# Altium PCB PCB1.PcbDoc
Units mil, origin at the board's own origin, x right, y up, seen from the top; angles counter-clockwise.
Board outline 4000.03 x 4245.03 mil, 2 copper layers (Top Layer, Bottom Layer); 64 components, 62 nets, 248 pads, 35 vias.
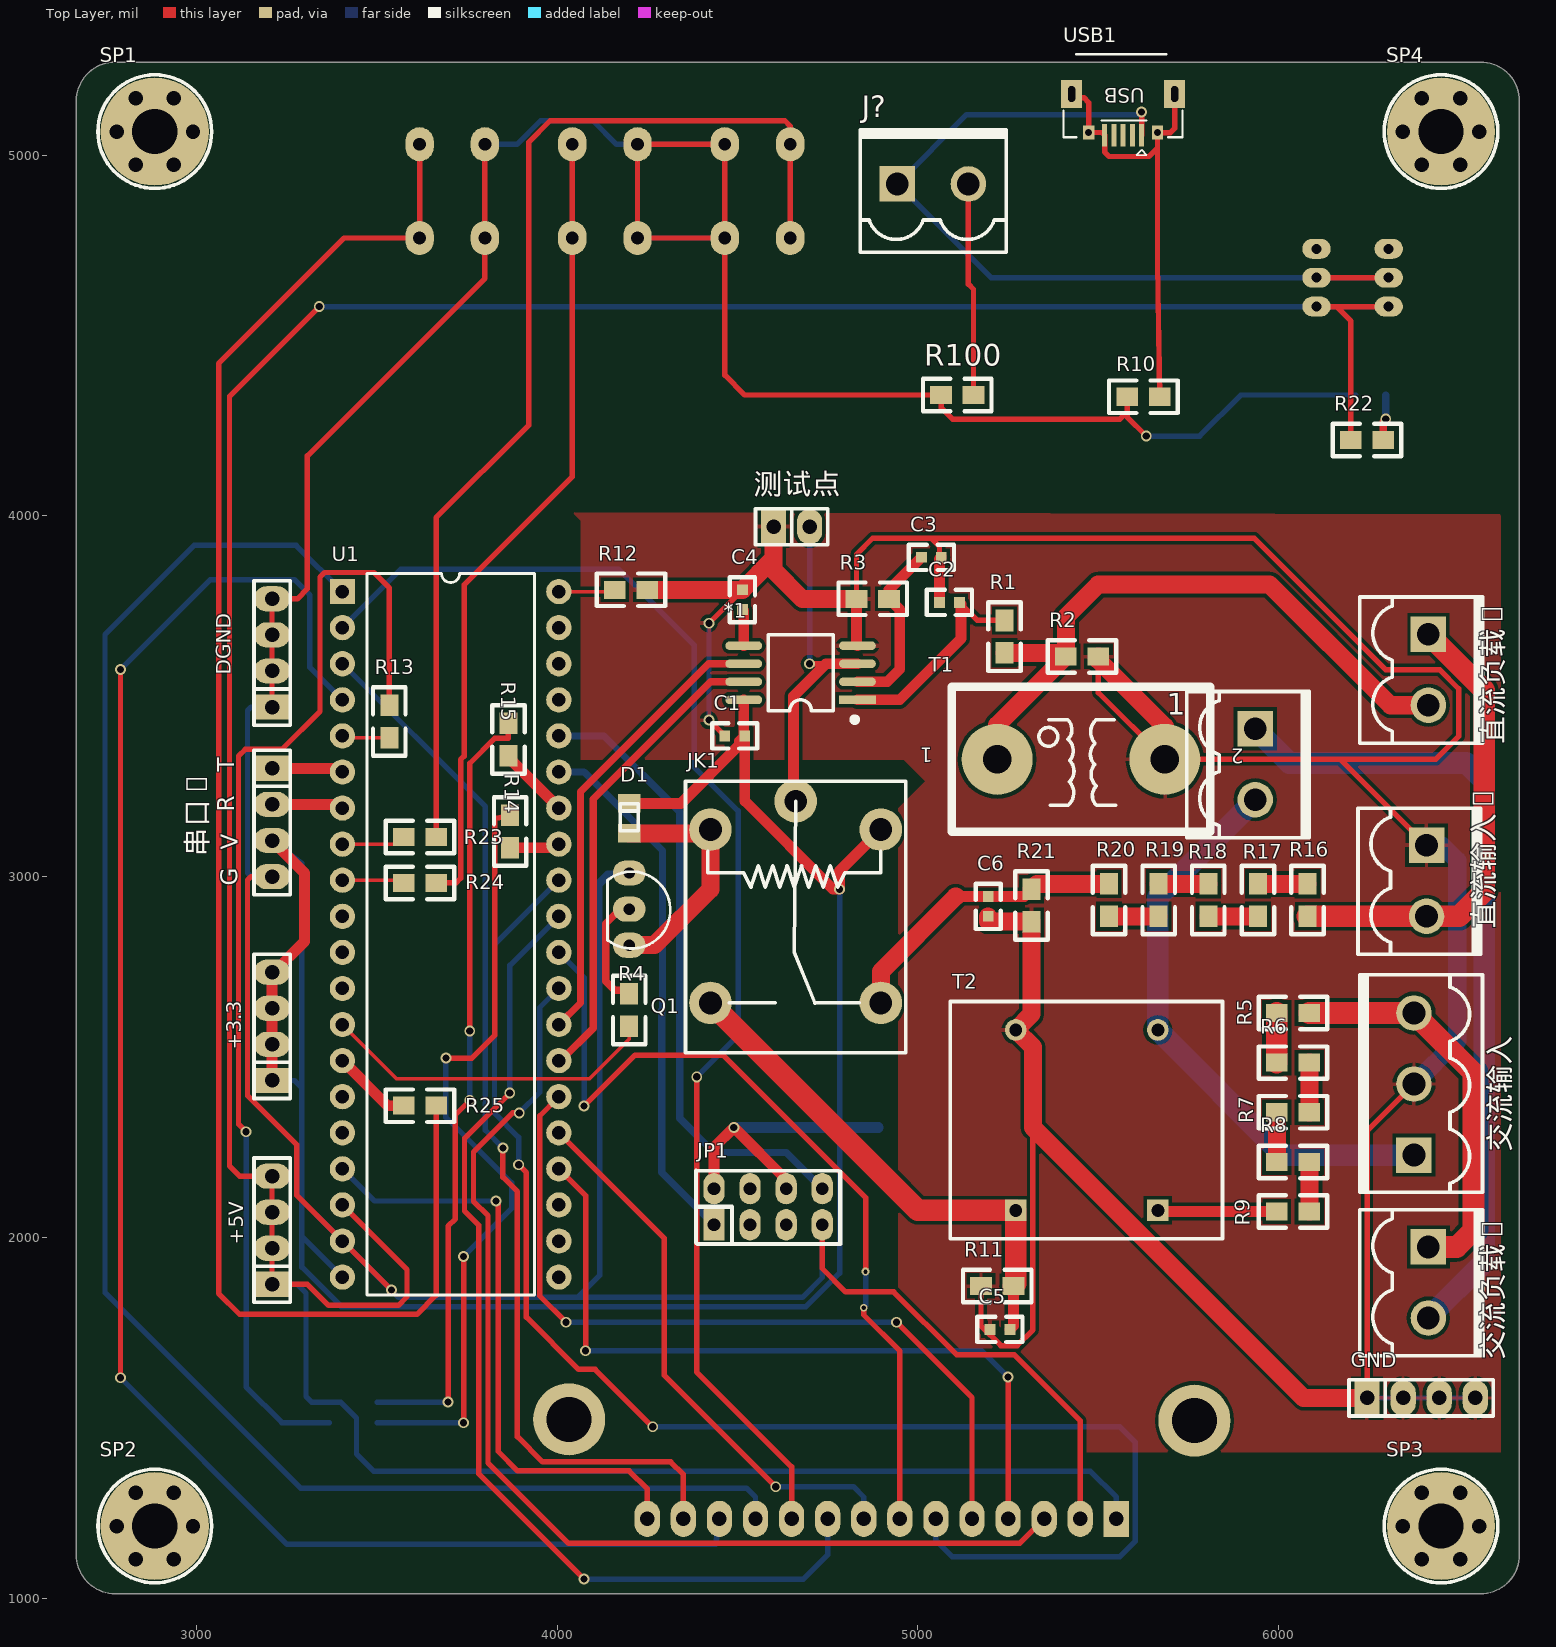
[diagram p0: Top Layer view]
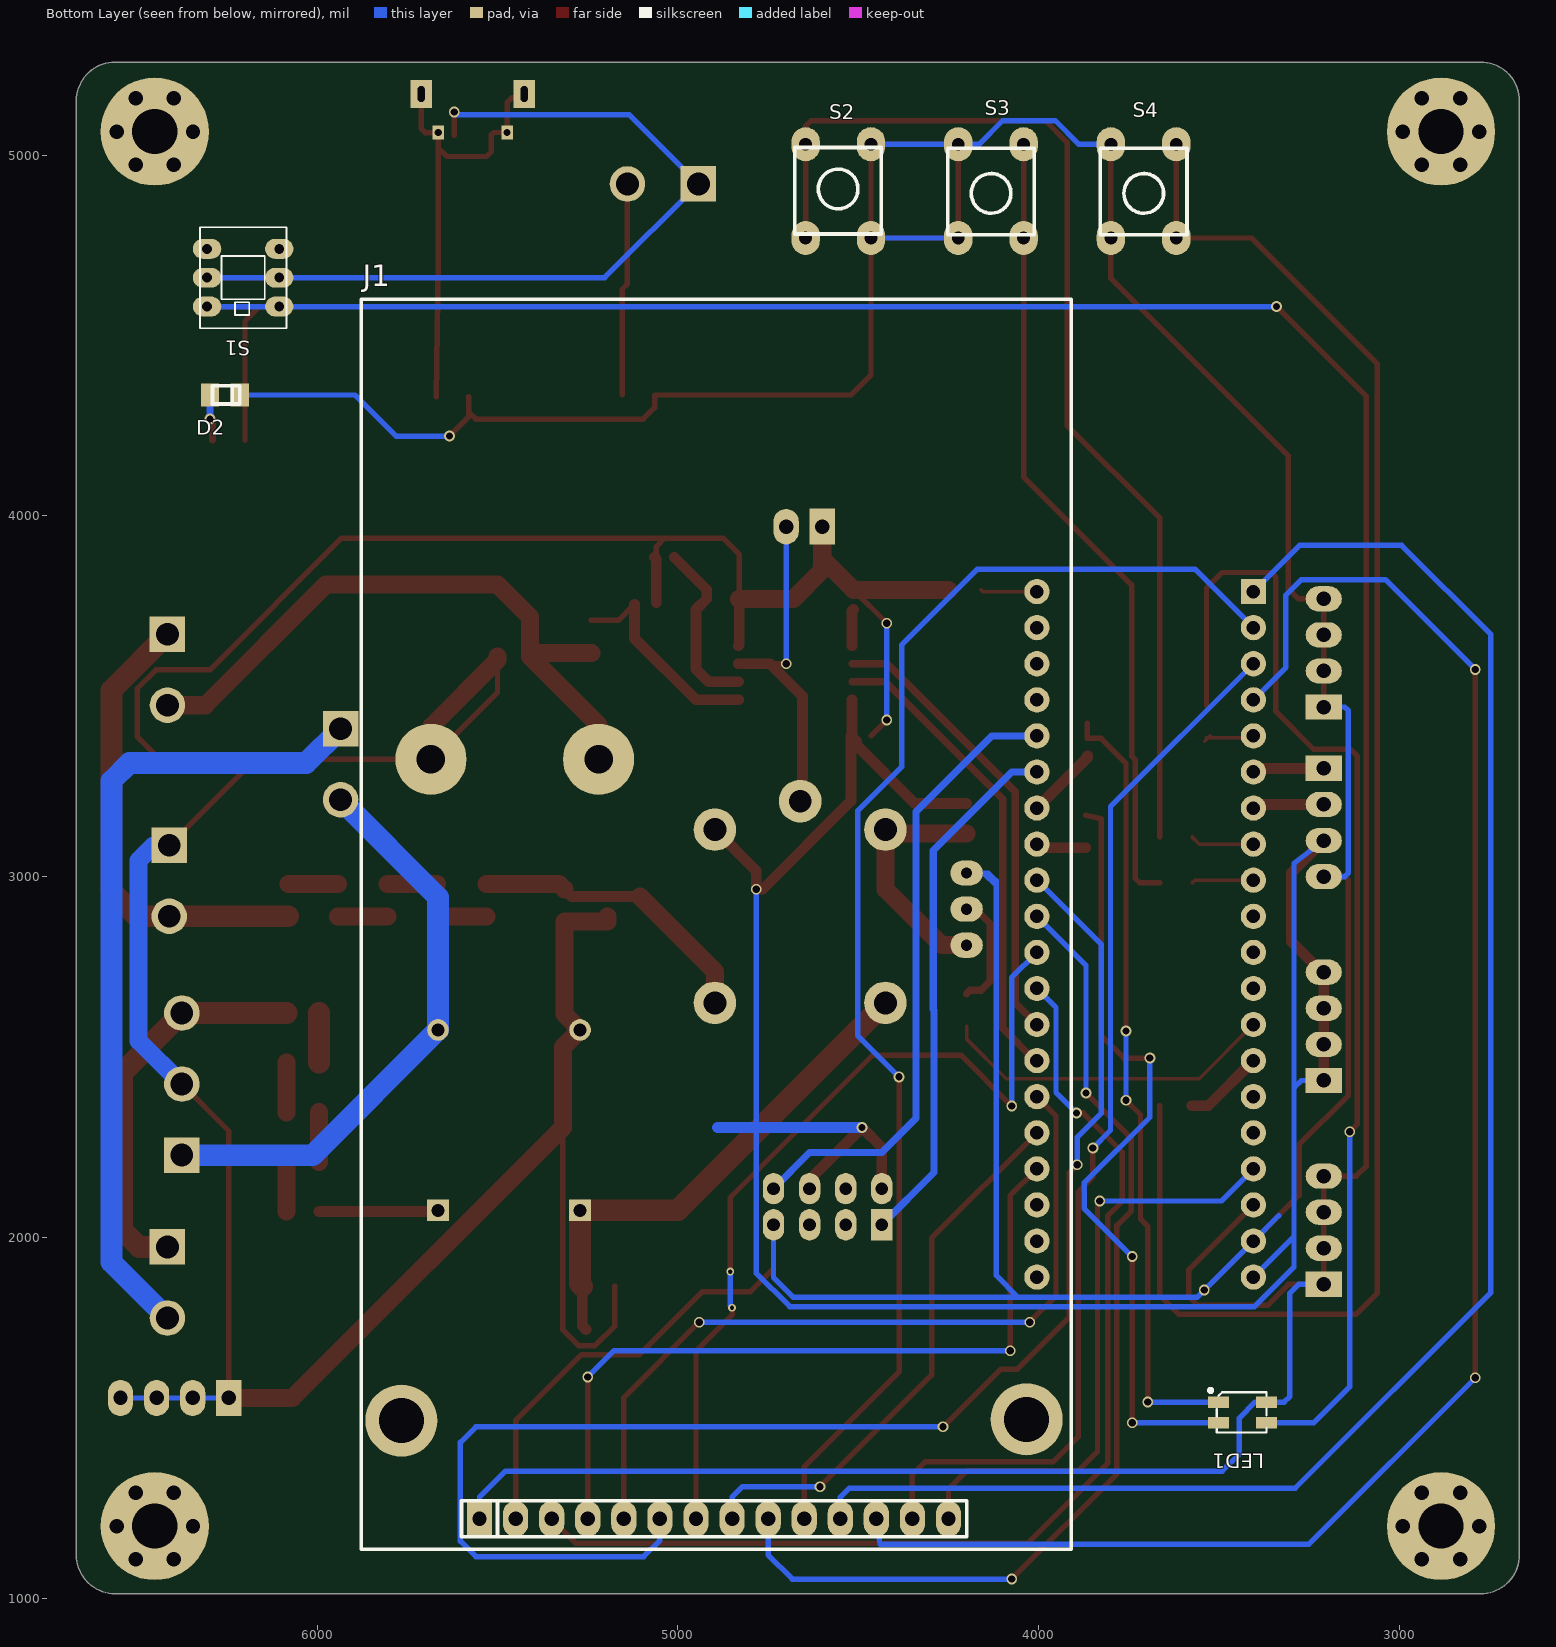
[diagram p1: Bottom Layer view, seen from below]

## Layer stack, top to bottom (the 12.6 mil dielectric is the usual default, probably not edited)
Top Solder: solder mask 0.4, Solder Resist, Dk 3.5
Top Layer: signal copper 1.4
Dielectric 1: dielectric 12.6, FR-4, Dk 4.8
Bottom Layer: signal copper 1.4
Bottom Solder: solder mask 0.4, Solder Resist, Dk 3.5

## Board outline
2667.49,1120 2667.49,5150 cw(c2775,5150) 2775,5257.52 6560,5257.52 cw(c6560,5150) 6667.52,5150 6667.52,1120 cw(c6560,1120) 6560,1012.49 2775,1012.49 cw(c2775,1120)

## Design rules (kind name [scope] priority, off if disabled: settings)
Clearance [All] p1: gap=10 ignorepadtopadclearanceinfootprint=FALSE except(0: Arc-Hole Track-Hole SMDPad-Hole THPad-Hole Via-Hole Fill-Hole Poly-Hole Region-Hole Text-Hole)
PolygonConnect [All] p1: connectstyle=Relief reliefconductorwidth=10 reliefentries=4 polygonreliefangle="90 Angle" airgapwidth=10
RoutingVias [All] p1: holewidth=28 width=50 viastyle="Through Hole" minholewidth=28 minwidth=50 maxholewidth=28 maxwidth=50
SolderMaskExpansion [All] p1: expansion=4
Width [All] p1: maxlimit=100 minlimit=10 preferedwidth=15
30 further rules are at their usual default settings.

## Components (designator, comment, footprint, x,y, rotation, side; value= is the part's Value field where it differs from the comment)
1 "导线" KF2EDGK5.0-LI-2P 5935,3311.57 r270 top
*1 "HLW8110" SOP8W_M 4675,3565 r180 top
+3.3 "CON4" sip-4 3210,2435 r90 top
+5V "CON4" sip-4 3210,1870 r90 top
C1 "0.1uf" 0603 4465,3390 r0 top
C2 "330nf" 0603 5115,3760 r180 top
C3 "330nf" 0603 5065,3885 r180 top
C4 "0.1uf" 0603 4513.78,3740 r90 top
C5 "33nf" 0603 5255,1745 r180 top
C6 "33nf" 0603 5195,2945 r270 top
D1 "1N4007" LED_0805 4200,3162 r90 top
D2 "LED" LED_0805 6255,4335 r180 bottom
DGND "CON4" sip-4 3210,3470 r90 top
GND "CON4" sip-4 6245,1555 r0 top
J1 "CON14" 2.8_LCD 4894.33,2535.91 r180 bottom
J? "CON2" KF2EDGK5.0-LI-2P 5041.57,4920 r0 top
JK1 "SRD-05VDC-SL-C" SRD-C_B 4897.44,3130.32 r270 top
JP1 "HEADER 4X2" IDC-8 4435,2035 r0 top
LED1 "RGB-3528" "LED 3528-4Pin" 3435,1515 r180 bottom
Q1 "SS8050" TO92A 4200,3010 r0 top
R1 "100R" 0805 5240,3620 r90 top
R2 "10R" 0805 5500,3610 r180 top
R3 "100R" 0805 4830,3770 r0 top
R4 "510" 0805 4200,2585 r90 top
R5 "20k" 0805 6085,2621.85 r180 top
R6 "20k" 0805 5995,2484.35 r0 top
R7 "20k" 0805 6085,2346.85 r180 top
R8 "20k" 0805 5995,2209.35 r0 top
R9 "20k" 0805 6085,2071.85 r180 top
R10 "0R" 0805 5580,4330 r0 top
R11 "100R" 0805 5175,1865 r0 top
R12 "0R" 0805 4250,3795 r180 top
R13 "510" 0805 3535,3385 r90 top
R14 "510" 0805 3870,3080 r90 top
R15 "310" 0805 3865,3335 r90 top
R16 "20K" 0805 6080,2890 r90 top
R17 "20K" 0805 5942.5,2980 r270 top
R18 "20K" 0805 5805,2890 r90 top
R19 "20K" 0805 5667.5,2980 r270 top
R20 "20K" 0805 5530,2890 r90 top
R21 "1k" 0805 5315,2875 r90 top
R22 "510" 0805 6200,4210 r0 top
R23 "510" 0805 3575,3110 r0 top
R24 "510" 0805 3575,2982.5 r0 top
R25 "510" 0805 3575,2365 r0 top
R100 "0R" 0805 5064.33,4335 r0 top
S1 "SW-DPDT" SWH7*7 6105,4740 r270 bottom
S2 "SW-PB" SW6*6 4646.1,4770 r90 bottom
S3 "SW-PB" SW6*6 4041.95,5029.84 r270 bottom
S4 "SW-PB" SW6*6 3618.9,5029.84 r270 bottom
SP1 "M3铜柱" M3x4+6_N 2885,5065 r0 top
SP2 "M3铜柱" M3x4+6_N 2885,1200 r0 top
SP3 "M3铜柱" M3x4+6_N 6450,1200 r0 top
SP4 "M3铜柱" M3x4+6_N 6450,5065 r0 top
T1 "Current transformer" ZMCT103E 5220,3325 r180 top
T2 "DA101C" ZMPT101B 5468.15,2325 r180 top
U1 "STM32F103C8T6核心板" STM32F103C8T6核心板 3810,2850 r0 top
USB1 "USB-5P" USB-MICRO_A 5568.82,5169.17 r180 top
串口1 "CON4" sip-4 3210,3300 r270 top
交流负载1 "负载" KF2EDGK5.0-LI-2P 6415,1875 r270 top
交流输入 "CON3" KF2EDGK5.0-LI-3P 6375,2425 r90 top
测试点 "测量点" sip-2 4600,3970 r0 top
直流负载1 "负载" KF2EDGK5.0-LI-2P 6415,3573.43 r270 top
直流输入1 "DC-IN" KF2EDGK5.0-LI-2P 6410,2988.43 r270 top

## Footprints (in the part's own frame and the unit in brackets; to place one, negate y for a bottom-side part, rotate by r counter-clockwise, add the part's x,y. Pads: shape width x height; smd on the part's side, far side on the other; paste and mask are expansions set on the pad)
2.8_LCD [mil]
  round 200 hole 125: 0(-872.2,-1043.82) 0(860.87,-1040.31)
  oval 70x100 hole 40: 1(644.33,-1315.91) 2(544.33,-1315.91) 3(444.33,-1315.91) 4(344.33,-1315.91) 5(244.33,-1315.91) 6(144.33,-1315.91) 7(44.33,-1315.91) 8(-55.67,-1315.91) 9(-155.67,-1315.91) 10(-255.67,-1315.91) 11(-355.67,-1315.91) 12(-455.67,-1315.91) 13(-555.67,-1315.91)
  rect 70x100 hole 40: 14(-655.67,-1315.91)
  silkscreen extent -984,-1400 985,2065, body extent -978,-1141 967,-948, height 159
0603 [mil]
  rect 30x30 smd: 1(0,0) 2(55,0)
  silkscreen extent -35,-35 90,35
0805 [mil]
  rect 60x50 smd: 1(0,0) 2(90,0)
  silkscreen extent -50,-45 140,45
IDC-8 [mm]
  rect 1.5x2.2 hole 0.9: 1(0,0)
  oval 1.5x2.2 hole 0.9: 2(0,2.54) 3(2.54,0) 4(2.54,2.54) 5(5.08,0) 6(5.08,2.54) 7(7.62,0) 8(7.62,2.54)
  silkscreen extent -1.27,-1.36 8.88,3.81
KF2EDGK5.0-LI-2P [mm] "立插端子                  淘宝ID:黄晶宝石"
  rect 2.5x2.5 hole 1.6: 1(-2.5,0)
  round 2.5 hole 1.6: 2(2.5,0)
  silkscreen extent -5.12,-4.83 5.17,3.81, body extent -5.04,-4.75 5.04,3.75, height 11.25
KF2EDGK5.0-LI-3P [mm] "立插端子"
  rect 2.5x2.5 hole 1.6: 1(-5,0)
  round 2.5 hole 1.6: 2(0,0) 3(5,0)
  silkscreen extent -7.62,-4.83 7.7,3.81, body extent -7.54,-4.75 7.54,3.75, height 11.25
"LED 3528-4Pin" [mm] "4脚，3528LED                             淘宝ID:黄晶宝石"
  rect 1.5x0.8 smd: 1(-1.689,0.725) 2(-1.689,-0.725) 3(1.689,-0.725) 4(1.689,0.725)
  silkscreen extent -2.37,-1.42 1.69,1.68, body extent -1.19,-1.19 1.2,1.19, height 1.95
LED_0805 [mm]
  rect 1.3x1.6 smd: 1(-1.067,0) 2(1.041,0)
  silkscreen extent -0.89,-0.64 1.02,0.64
M3x4+6_N [mil] "M3铜柱，长：4mm，螺纹长：6mm"
  round 40 hole 40: 1(-106,0) 1(-53,-91.8) 1(-53,91.8) 1(53,-91.8) 1(53,91.8) 1(106,0)
  round 300 hole 125: 1(0,0)
  silkscreen extent -157,-157 157,157, body extent -106,-93 106,93, height 159
sip-2 [mil]
  rect 70x100 hole 40: 1(0,0)
  oval 70x98.42 hole 40: 2(100,0)
  silkscreen extent -50,-50 150,50
sip-4 [mil]
  rect 70x100 hole 40: 1(0,0)
  oval 70x100 hole 40: 2(100,0) 3(200,0) 4(300,0)
  silkscreen extent -50,-50 350,50
SOP8W_M [mm] "5.3*8.3*1.8mm（长宽高）  淘宝ID:黄晶宝石"
  rect 2.6x0.6 smd: 1(-4,1.905)
  oval 2.6x0.6 smd: 2(-4,0.635) 3(-4,-0.635) 4(-4,-1.905) 5(4,-1.905) 6(4,-0.635) 7(4,0.635) 8(4,1.905)
  silkscreen extent -3.94,-2.67 2.29,3.43, body extent -3.94,-2.64 3.94,2.64, height 1.9
SRD-C_B [mm] "单刀双投                  淘宝ID:黄晶宝石"
  round 3 hole 1.6: 1(0,0) 2(0,-12) 3(-2,-6) 4(12.2,0) 5(12.2,-12)
  silkscreen extent -3.4,-13.75 15.7,1.75, body extent -3.4,-13.75 15.7,1.75, height 15.6
STM32F103C8T6核心板 [mil]
  round 70 hole 37.4: 1(195,940) 2(195,840) 3(195,740) 4(195,640) 5(195,540) 6(195,440) 7(195,340) 8(195,240) 9(195,140) 10(195,40) 11(195,-60) 12(195,-160) 13(195,-260) 14(195,-360) 15(195,-460) 16(195,-560) 17(195,-660) 18(195,-760) 19(195,-860) 20(195,-960) 21(-405,-960) 22(-405,-860) 23(-405,-760) 24(-405,-660) 25(-405,-560) 26(-405,-460) 27(-405,-360) 28(-405,-260) 29(-405,-160) 30(-405,-60) 31(-405,40) 32(-405,140) 33(-405,240) 34(-405,340) 35(-405,440) 36(-405,540) 37(-405,640) 38(-405,740) 39(-405,840)
  rect 70x70 hole 37.4: 40(-405,940)
  silkscreen extent -337,-1010 127,990
SW6*6 [mm]
  oval 2.4x2 hole 0.9: 1(0,0) 1(6.6,0) 2(0,-4.6) 2(6.6,-4.6)
  silkscreen extent 0.28,-5.34 6.38,0.76
SWH7*7 [mm]
  oval 1.4x2 hole 0.7: 1(0,0) 2(2.032,0) 3(4.064,0) 4(4.064,-5.08) 5(2.032,-5.08) 6(0,-5.08)
  silkscreen extent -1.52,-5.59 5.59,0.51
TO92A [mil]
  oval 90x70 hole 31.5: 1(0,0) 2(0,-100) 3(0,-200)
  silkscreen extent -60,-209 114,4
USB-MICRO_A [mm] "micro型USB ，5.7*7.8*2.5mm"
  rect 0.35x1.6 smd: 1(-1.3,2.9) 2(-0.65,2.9) 3(0,2.9) 4(0.65,2.9) 5(1.3,2.9)
  rect 1.5x2 hole 0.5 slot 1.1 at 90 deg: 5(-3.625,0) 5(3.625,0)
  rect 0.8x1 hole 0.5: 5(-2.425,2.71) 5(2.425,2.71)
  silkscreen extent -4.19,-2.79 4.19,4.3, body extent -4,-2.71 4,2.89, height 2.8
ZMCT103E [mm] "102mm*182mm"
  round 5 hole 2: 1(0,0) 2(-11.8,0)
  silkscreen extent -15,-5.1 3.2,5.1
ZMPT101B [mil]
  rect 60x60 hole 35.98: 1(-196.85,250) 3(196.85,250)
  round 60 hole 35.98: 2(-196.85,-250) 4(196.85,-250)
  silkscreen extent -376,-329 378,329

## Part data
1 R1 R2 R3 R4 R5 R6 R7 R8 R9 R10 R11 R12 R13 R14 R15 R16 R17 R18 R19 R20 R21 R22 R23 R24 R25 R100 交流负载1 直流负载1: library part RES, "电阻"
+3.3 +5V DGND GND J1 J? 串口1 交流输入: "Connector"
C1 C2 C3 C4 C5 C6: library part CAP1
D1: library part DIODE
JK1: "5V一组转换"
LED1: library part "LED-RGB 3528", "3528三基色LED"
Q1: library part 8050-DIP, "高频放大-NPN型"
SP1 SP2 SP3 SP4: library part 铜柱加头大焊盘, "铜柱"
T2: library part DA10XC, "数字隔离变压器"
USB1: "微型USB母座"
测试点 直流输入1: library part CON2, "Connector"

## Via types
v1: diameter 30, hole 20, Top Layer to Bottom Layer, 26 vias
v2: diameter 30, hole 20, Top Layer to Bottom Layer, tented both sides, 7 vias
v3: diameter 22, hole 12, Top Layer to Bottom Layer, 2 vias

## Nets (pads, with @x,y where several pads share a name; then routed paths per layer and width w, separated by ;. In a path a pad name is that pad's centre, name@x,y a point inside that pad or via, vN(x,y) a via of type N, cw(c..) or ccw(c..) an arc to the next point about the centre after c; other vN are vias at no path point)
+3.3V: *1.8 +3.3.1 +3.3.2 +3.3.3 +3.3.4 C1.2 D1.2 JK1.1 JP1.2 JP1.6 U1.21 串口1.3 | length 6938.3
  Top Layer w30: +3.3.1 +3.3.2 +3.3.3 +3.3.4 3215,2735 3300,2820 3300,3010 串口1.3 ; D1.2 4343.36,3203 4505,3364.64 4505,3375 C1.2 ; JP1.2 4435,2250 v2(4490,2305) 4635,2160 JP1.6 ; *1.8 4517.52,3392.48 C1.2 ; JK1.1 4783,3015.87 v2(4783,2965) 4765,2965 4520,3210 C1.2
  Bottom Layer w15: +3.3.1 3272,2435 3292,2415 ; 串口1.3 3292.5,3037.5 3292.5,2002.5 ; U1.21 3292.5,2002.5 ; v2(4783,2965) 4783,1901 4690,1808 3402,1808 3292.5,1917.5 3292.5,2002.5
  Bottom Layer w30: v2(4490,2305) 4890,2305
+5V: +5V.1 +5V.2 +5V.3 +5V.4 J1.14 LED1.4 R22.1 S1.3 S1.4 U1.23 | length 10072.6
  Top Layer w15: v1(3341,4580) 3092,4331 3092,2198 3120,2170 +5V.4 +5V.3 +5V.2 +5V.1 3308,1870 3366.5,1811.5 3560,1811.5 3584,1835.5 3584,1911 U1.23 ; S1.3 6160,4580 ; R22.1 6200,4540 6160,4580 ; S1.4 6160,4580
  Bottom Layer w15: +5V.1 3280,1870 3304,1846 3304,1559.54 3320,1543.54 LED1.4 3400,1543.54 3444,1499.54 3444,1400 3491.59,1352.41 5477.59,1352.41 5550,1280 J1.14 ; v1(3341,4580) S1.3 S1.4
AC_C: C5.1 JK1.5 R11.2 T2.3 | length 1421.2
  Top Layer w30: C5.1 5265,1755 R11.2
  Top Layer w60: JK1.5 5000,2075 T2.3 5271.3,1871.3 R11.2
connect_1: R1.1 R2.2 T1.1 直流负载1.2 | length 1828.9
  Top Layer w50: T1.1 5220,3420 R2.2 ; R1.1 5400,3620 R2.2 ; 直流负载1.2 6310,3475 5975,3810 5500,3810 5410,3720 R2.2
CS: J1.12 U1.12 | length 3102.1
  Top Layer w15: v1(3895,2345) 3876.79,2345 3768.5,2236.71 3768.5,2100.13 3808.5,2060.13 3808.5,1375.22 4031.72,1152 5282,1152 J1.12
  Bottom Layer w15: v1(3895,2345) 3952,2402 3952,2637 U1.12
DC: J1.10 U1.15 | length 2224.8
  Top Layer w15: U1.15 3952,2337 3952,1838 v1(4025,1765) ; v1(4941,1765) 5150,1556 J1.10
  Bottom Layer w15: v1(4025,1765) v1(4941,1765)
DC_C: C6.1 JK1.4 R20.2 R21.2 | length 820.5
  Top Layer w30: 5105,2945 C6.1 5295,2945 R21.2
  Top Layer w50: JK1.4 4897.44,2737.44 5105,2945 ; R21.2 5330,2980 R20.2
DGND: D2.2 DGND.1 DGND.2 DGND.3 DGND.4 J1.13 JP1.7 Q1.1 R10.1 R100.1 S2.2 S3.2 S4.2 U1.22 串口1.4 | length 13677.1
  Top Layer w15: 串口1.4 3152,3000 3142,2990 3142,2393 3278,2257 3278,2117 U1.22 v1(3541,1854) ; DGND.1 DGND.2 DGND.3 DGND.4 3280,3770 3308,3798 3308,4166 3800,4658 3800,4770 S4.2@3800,5029.84 ; JP1.7 4735,1914 4800,1849 4933,1849 5107,1675 5267,1675 5450,1492 J1.13 ; R10.1 5580,4288 ; v1(5633,4221) 5580,4274 5580,4288 ; S2.2@4465,4770 4223.05,4770 4223.05,5029.84 4465,5029.84 S2.2@4465,4770 ; S2.2@4465,4770 4465,4390 4520,4335 R100.1 5064.33,4300 5096.33,4268 5560,4268 5580,4288
  Bottom Layer w15: 串口1.4 3152,3000 3142,3010 3142,3460 3152,3470 DGND.1 ; 3335,2060 U1.22 ; S4.2@3800,5029.84 3888.84,5029.84 3954,5095 4099.84,5095 4165,5029.84 4223.05,5029.84 S2.2@4465,5029.84 ; Q1.1 4152.5,3010 ; S3.2@4223.05,4770 S2.2@4465,4770 ; JP1.7 4735,1889 4680,1834 4057,1834 ; v1(5633,4221) 5781,4221 5895,4335 D2.2 ; U1.22 3561,1834 ; U1.22 v1(3541,1854) 3561,1834 ; 3561,1834 4057,1834 ; 4057,1834 4117.5,1894.5 ; 4117.5,1894.5 4118,1895 4118,2988 4140,3010 4152.5,3010 ; 4117.5,1894.5 4117.5,2975 4152.5,3010
GND: *1.4 C1.1 C2.2 C3.1 C4.2 C5.2 C6.2 GND.1 GND.2 GND.3 GND.4 R2.1 R3.1 R11.1 R12.1 R21.1 T1.2 T2.4 交流输入.2 测试点.1 直流输入1.1 | length 10544.7
  Top Layer w15: v2(4421,3434) C1.1 ; v2(4421,3702.22) C4.2 ; R3.1 4830,3893 4875,3938 5037,3938 ; C2.2 5060,3880 5060,3915 5037,3938 ; R11.1 5175,1770 5175,1755 5230,1700 5275,1700 5319,1744 5319,2326 ; R2.1 5500,3600 5500,3510 5684.57,3325.43 T1.2@5685,3325 ; T1.2 T1.2@5685,3325 ; GND.1 6245,1936 6245,2295 交流输入.2 ; 直流输入1.1 6171.85,3325 ; 5037,3938 5932,3938 6297,3573 6446.67,3573 6499,3520.67 6499,3389 6435,3325 6171.85,3325 ; T1.2@5685,3325 6171.85,3325
  Top Layer w30: R3.1 4830,3642.48 *1.4 ; C2.2 5060,3880 C3.1
  Top Layer w50: R12.1 C4.2 4600,3881.22 ; 测试点.1 4600,3881.22 ; R3.1 4679.64,3770 4600,3849.64 4600,3881.22 ; C6.2 5195,2875 R21.1 5315,2618.7 T2.4 5319,2527.3 5319,2326 5319,2305 6069,1555 GND.1 ; R2.1 5500,3600 5684.57,3415.43 T1.2
  Bottom Layer w15: v2(4421,3434) v2(4421,3702.22) ; GND.1 GND.2 GND.3 GND.4
  Bottom Layer w50: 交流输入.2 6495,2545 6495,3045 6453.15,3086.85 直流输入1.1
L: R5.1 交流负载1.1 交流输入.3 | length 1104.5
  Top Layer w60: R5.1 交流输入.3 6540,2456.85 6540,2020 6493.43,1973.43 交流负载1.1
LED_BACK: J1.7 U1.16 | length 1546
  Top Layer w15: U1.16 4297,1998 4297,1618 v1(4606,1309)
  Bottom Layer w15: v1(4606,1309) 4821,1309 4850,1280 J1.7
MISO: J1.6 U1.10 | length 2885.4
  Top Layer w15: v1(3869,2400) 3743.5,2274.5 3743.5,2073.5 3783.5,2033.5 3783.5,1344.5 v1(4075,1053)
  Bottom Layer w15: v1(3869,2400) 3869,2754 U1.10 ; v1(4075,1053) 4683,1053 4750,1120 J1.6
MOSI: J1.9 U1.9 | length 4076.8
  Top Layer w15: v1(3893.5,2201.5) 3915,2180 3915,1779 4059.78,1634.23 4105.77,1634.23 v1(4265,1475)
  Bottom Layer w15: v1(3893.5,2201.5) 3893.5,2277.46 3826.5,2344.46 3826.5,2811.5 U1.9 ; v1(4265,1475) 5560,1475 5603,1432 5603,1158 5560,1115 5095,1115 5050,1160 J1.9
N: 1.2 T2.2 交流输入.1 | length 1603.7
  Bottom Layer w60: 1.2 5665,2943.15 T2.2 6011.85,2228.15 交流输入.1
Net1_1: 1.1 交流负载1.2 | length 2247.7
  Bottom Layer w60: 1.1 6030,3315 6520,3315 6570,3265 6570,1931.57 交流负载1.2
Net*1_1: *1.1 C2.1 R1.2 | length 608.6
  Top Layer w15: R1.2 5165,3710 C2.1@5120,3755 ; C2.1@5120,3755 5115,3755 C2.1 C2.1@5120,3755
  Top Layer w30: *1.1 4950,3490 5120,3660 C2.1@5120,3755
Net*1_2: *1.2 C3.2 R3.2 | length 491.7
  Top Layer w30: *1.2 4915,3540 4950,3575 4950,3740 R3.2 4920,3795 C3.2
Net*1_3: *1.3 JK1.3 测试点.2 | length 1020.8
  Top Layer w15: v2(4700,3590) 4745,3590 *1.3
  Top Layer w30: JK1.3 4655,3215.28 4655,3500 4745,3590 *1.3
  Bottom Layer w15: v2(4700,3590) 测试点.2
Net*1_5: *1.5 C4.1 | length 101.5
  Top Layer w30: C4.1 4517.52,3736.26 *1.5
NetD1_1: D1.1 JK1.2 Q1.3 | length 683.8
  Top Layer w50: Q1.3 4270,2810 4425,2965 JK1.2 4414.69,3120 D1.1
NetD2_1: D2.1 R22.2 | length 132.1
  Top Layer w20: R22.2 6290,4261 v2(6297,4268)
  Bottom Layer w20: D2.1 v2(6297,4268) v2@6300,4265
NetJ?_2: J?.2 R100.2 | length 590.9
  Top Layer w15: J?.2 5140,4642.33 5154.33,4628 R100.2
NetLED1_1: LED1.1 R15.2 | length 2169.4
  Top Layer w15: v1(3698,1543.54) 3698,2031.5 3718,2051.5 3718,2340 v1(3758,2380) ; v1(3758,2572) 3758,3314 3827,3383 3865,3383 R15.2
  Bottom Layer w15: LED1.1 v1(3698,1543.54) ; v1(3758,2380) v1(3758,2572)
NetLED1_2: LED1.2 R14.2 | length 2185.8
  Top Layer w15: v1(3692,2497) 3764,2497 3827,2560 3827,3160 R14.2 ; v1(3741,1486.46) v1(3741,1947)
  Bottom Layer w15: LED1.2 v1(3741,1486.46) ; v1(3692,2497) 3692,2333 3874,2151 3874,2080 v1(3741,1947)
NetLED1_3: LED1.3 R13.2 | length 3218.3
  Top Layer w15: v1(3138,2293) 3117,2314 3117,3334 3136,3353 3238,3353 3343,3458 3343,3830 3356,3843 3492,3843 3535,3800 R13.2
  Bottom Layer w15: v1(3138,2293) 3138,1585.46 3237,1486.46 LED1.3
NetQ1_2: Q1.2 R4.2 | length 321.1
  Top Layer w20: R4.2 4190,2685 4160,2685 4135,2710 4135,2870 4175,2910 Q1.2
NetR5_2: R5.2 R6.1 | length 137.5
  Top Layer w60: R6.1 R5.2
NetR6_2: R6.2 R7.1 | length 137.5
  Top Layer w50: R7.1 R6.2
NetR7_2: R7.2 R8.1 | length 137.5
  Top Layer w50: R8.1 R7.2
NetR8_2: R8.2 R9.1 | length 137.5
  Top Layer w50: R9.1 R8.2
NetR9_2: R9.2 T2.1 | length 331.3
  Top Layer w30: T2.1 5668.15,2071.85 R9.2
NetR10_2: R10.2 USB1.5 | length 1282
  Top Layer w15: USB1.5@5426.1,5169.17 5426.1,5159 5460,5159 5473.35,5145.65 5473.35,5062.48 5510.16,5062.48 5517.64,5055 5517.64,5008.36 5530,4996 5640.29,4996 5664.29,5020 ; USB1.5@5664.29,5062.48 USB1.5@5664.29,5062 ; R10.2 5664.29,4701.71 5664.29,5020 ; USB1.5@5711.54,5169.17 5711.54,5073.54 5700,5062 USB1.5@5664.29,5062 ; 5664.29,5020 USB1.5@5664.29,5062
NetR12_2: R12.2 U1.1 | length 157.1
  Top Layer w10: U1.1 4155,3790 R12.2
NetR16_1: R16.1 直流负载1.1 直流输入1.2 | length 1295
  Top Layer w60: R16.1 直流输入1.2 6500,2890 6570,2960 6570,3516.85 直流负载1.1
NetR16_2: R16.2 R17.1 | length 137.5
  Top Layer w50: R17.1 R16.2
NetR17_2: R17.2 R18.1 | length 137.5
  Top Layer w50: R18.1 R17.2
NetR18_2: R18.2 R19.1 | length 137.5
  Top Layer w50: R19.1 R18.2
NetR19_2: R19.2 R20.1 | length 137.5
  Top Layer w50: R20.1 R19.2
NetR23_2: R23.2 S2.1 | length 3097.2
  Top Layer w15: R23.2 3665,3995 3921,4251 3921,5035 3981,5095 4631.1,5095 4646.1,5080 4646.1,5029.84 S2.1@4646.1,4770
NetR24_2: R24.2 S3.1 | length 2235.7
  Top Layer w15: R24.2 3720,2982.5 3733,2995.5 3733,3324.36 3742.5,3333.86 3742.5,3808.5 4041.95,4107.95 4041.95,4770 S3.1@4041.95,5029.84
NetR25_2: R25.2 S4.1 | length 4712.3
  Top Layer w15: S4.1@3618.9,5029.84 3618.9,4770 3410,4770 3062,4422 3062,1845 3120.5,1786.5 3611.5,1786.5 3665,1840 R25.2
PA11: R23.1 U1.33 | length 178.3
  Top Layer w10: U1.33 3555,3090 R23.1
PA12: R24.1 U1.32 | length 173.1
  Top Layer w10: U1.32 3567.5,2990 R24.1
PB5: R4.1 U1.28 | length 937.7
  Top Layer w10: U1.28 3555,2440 4090,2440 4200,2550 R4.1
PB6: R25.1 U1.27 | length 221.8
  Top Layer w30: U1.27 3530,2365 R25.1
Power_In: J?.1 S1.2 S1.5 USB1.1 | length 2492.8
  Top Layer w15: USB1.1 v1(5620,5119) ; S1.2 S1.5
  Bottom Layer w15: v1(5620,5119) 5613,5112 5135.15,5112 J?.1 5203.15,4660 S1.2 S1.5
RST: J1.11 U1.17 | length 2128.9
  Top Layer w15: U1.17 4079,2116 v1(4079,1686) ; J1.11 v1(5250,1613)
  Bottom Layer w15: v1(4079,1686) 5177,1686 v1(5250,1613)
RX_measure: *1.6 U1.13 | length 1269.4
  Top Layer w20: U1.13 4065,2650 4065,3235 4420,3590 *1.6
RX_PC: U1.34 串口1.2 | length 199.1
  Top Layer w30: 串口1.2 3395,3200 U1.34
RX_WIFI: JP1.8 U1.5 | length 1747.8
  Bottom Layer w20: U1.5 4130,3390 4340,3180 4340,2330 4435,2235 4635,2235 JP1.8
SCK: J1.8 U1.11 | length 2390.5
  Top Layer w15: v2(4075,2364) 4216,2505 4460,2505 4855,2110 v3(4855,1905) ; v3(4850,1805) 4850,1785 4950,1685 J1.8
  Bottom Layer w15: U1.11 4075,2720 v2(4075,2364) ; v3(4850,1805) 4855,1810 v3(4855,1905)
SPI2_MISO: J1.2 U1.38 | length 2969.4
  Top Layer w15: v1(3850,2248) 3850,2167 3890,2127 3890,1448 3960,1378 4315,1378 4350,1343 J1.2
  Bottom Layer w15: U1.38 3801,3194 3801,2297 v1(3850,2248)
SPI2_MOSI: J1.3 U1.37 | length 4849.3
  Top Layer w15: v1(2790,1611) v1(2790,3574)
  Bottom Layer w15: v1(2790,1611) 3252,1149 4440,1149 J1.3 ; v1(2790,3574) 3039,3823 3272,3823 3315,3780 3315,3580 U1.37
SPI2_NSS: J1.4 U1.40 | length 4735.2
  Bottom Layer w15: U1.40 3277,3918 2994,3918 2747,3671 2747,1847 3289,1305 4525,1305 4550,1280 J1.4
SPI2_SCK: J1.5 U1.39 | length 3758.2
  Top Layer w15: v1(4387,2445) 4387,1627 4650,1364 J1.5
  Bottom Layer w15: U1.39 3567,3852 4170,3852 4380,3642 4380,3304 4502,3182 4502,2560 v1(4387,2445)
TFT_PB9: J1.1 U1.24 | length 1698.5
  Top Layer w15: v1(3831,2101) 3837,2095 3837,1406.96 3890.96,1353 4200,1353 4250,1303 J1.1
  Bottom Layer w15: U1.24 3494,2101 v1(3831,2101)
TIM1_CH1: R13.1 U1.36 | length 156.8
  Top Layer w10: U1.36 3410,3385 R13.1@3530,3385 ; R13.1@3525,3390 R13.1@3530,3385 ; R13.1@3532.5,3382.5 R13.1@3530,3385 ; R13.1 R13.1@3530,3385 ; R13.1@3540,3375 R13.1@3530,3385
TIM3_TH3: R14.1 U1.8 | length 139.1
  Top Layer w30: R14.1 3995,3080 U1.8
TIM3_TH4: R15.1 U1.7 | length 203
  Top Layer w30: R15.1 3865,3330 U1.7
TX_measure: *1.7 U1.14 | length 1319.4
  Top Layer w20: U1.14 4010,2490 4100,2580 4100,3215 4425,3540 *1.7
TX_PC: U1.35 串口1.1 | length 199.1
  Top Layer w10: U1.35@3395,3300 U1.35
  Top Layer w30: 串口1.1 U1.35@3395,3300
TX_WIFI: JP1.1 U1.6 | length 1476.2
  Bottom Layer w20: U1.6 4075,3290 4292.5,3072.5 4292.5,2632.5 4290,2630 4290,2180 JP1.1
pads on no net: J1.0 JP1.3 JP1.4 JP1.5 S1.1 S1.6 SP1.1 SP2.1 SP3.1 SP4.1 U1.2 U1.3 U1.4 U1.18 U1.19 U1.20 U1.25 U1.26 U1.29 U1.30 U1.31 USB1.2 USB1.3 USB1.4

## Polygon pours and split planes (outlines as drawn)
GND on Bottom Layer "Bottom Layer-GND 1" (solid, remove dead copper, pour order 16): 4965,5170
GND on Top Layer (solid, remove dead copper, pour order 26): 4041.95,4010 4065,3986.95 4065,3324.36 4960.64,3324.36 5020,3265 4945,3190 4945,1455 4995,1405 6615,1405 6615,4000 6620,4005

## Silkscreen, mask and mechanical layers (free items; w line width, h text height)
Top Overlay:
  text "T" at 3120,3290 h80 r90
  text "R" at 3120,3180 h80 r90
  text "V" at 3130,3075 h80 r90
  text "G" at 3130,2975 h80 r90
Mechanical 1:
  lines w15: 2675,5050 2675,5150 cw(c2775,5150) 2775,5250 5655,5250 6560,5250 cw(c6560,5150) 6660,5150 6660,1245 6660,1120 cw(c6560,1120) 6560,1020 2895,1020 2775,1020 cw(c2775,1120) 2675,1120 2675,5060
